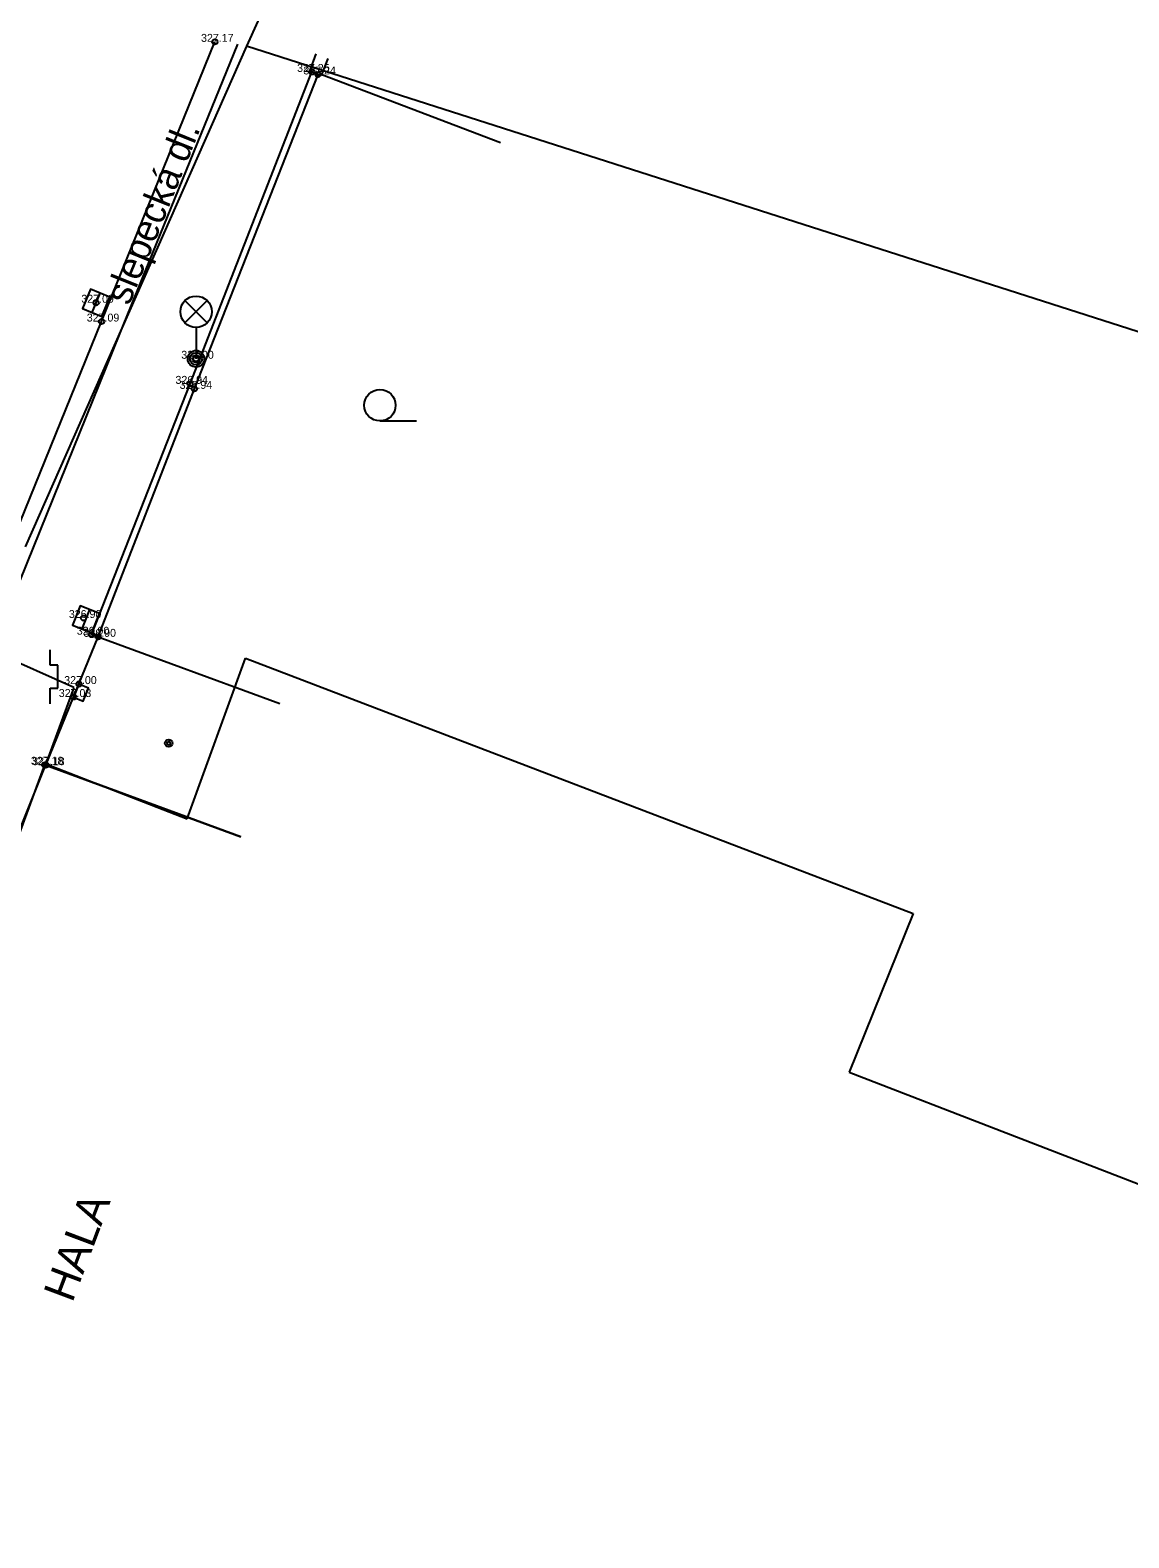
# Model space of a CAD drawing. Extents: x -643859 to -643594, y -1190913 to -1190609.
# Drawn here: x -643684.48 to -643658.2, y -1190805.4 to -1190769.34 of the extents above; entities that cross this region are included whole.
import ezdxf

# ---------------------------------------------------------------- set-up
doc = ezdxf.new("R2010")
doc.units = 0
for name, color, linetype in [('Bodové objekty elektro', 7, 'Continuous'), ('Bodové objekty kanalizace', 7, 'Continuous'), ('Bodové objekty katastrální', 7, 'Continuous'), ('Bodové objekty polohopis', 7, 'Continuous'), ('Bodové objekty značky budov', 7, 'Continuous'), ('Bodové objekty značky předmětů', 7, 'Continuous'), ('Budovy', 7, 'Continuous'), ('Default', 7, 'Continuous'), ('Hranice parcel', 7, 'Continuous'), ('Osa kolejí', 7, 'Continuous'), ('Ploty_podezdívky', 7, 'Continuous'), ('Popis povrchů', 7, 'Continuous'), ('Rozhraní', 7, 'Continuous'), ('Rozhraní_ schody_ zdi', 7, 'Continuous'), ('Svodidla_zábradlí', 7, 'Continuous')]:
    doc.layers.add(name, color=color, linetype=linetype)

msp = doc.modelspace()

# ---------------------------------------------------------------- linework, layer by layer
at = {"layer": 'Bodové objekty elektro'}
for p, q in [((-643683.999, -1190784.529), (-643684, -1190784.161)), ((-643683.816, -1190784.53), (-643683.999, -1190784.529)), ((-643683.816, -1190785.082), (-643683.816, -1190784.53)), ((-643684, -1190785.45), (-643683.999, -1190785.082)), ((-643683.999, -1190785.082), (-643683.816, -1190785.082))]:
    msp.add_line(p, q, dxfattribs=at)
at = {"layer": 'Bodové objekty kanalizace'}
for p, q in [((-643682.995, -1190776.091), (-643682.805, -1190775.629)), ((-643683.232, -1190783.662), (-643683.048, -1190783.198))]:
    msp.add_line(p, q, dxfattribs=at)
for points in [[(-643682.764, -1190776.186), (-643682.574, -1190775.724), (-643683.036, -1190775.534), (-643683.226, -1190775.996)], [(-643683, -1190783.754), (-643682.816, -1190783.29), (-643683.28, -1190783.106), (-643683.464, -1190783.57)]]:
    msp.add_lwpolyline(points, close=True, dxfattribs=at)
at = {"layer": 'Bodové objekty katastrální'}
msp.add_line((-643676.112, -1190778.688), (-643675.237, -1190778.688), dxfattribs=at)
msp.add_circle((-643676.112, -1190778.313), 0.375, dxfattribs=at)
at = {"layer": 'Bodové objekty polohopis'}
for p, q in [((-643680.775, -1190776.34), (-643680.245, -1190775.81)), ((-643680.775, -1190775.81), (-643680.245, -1190776.34)), ((-643680.51, -1190776.45), (-643680.51, -1190777.2))]:
    msp.add_line(p, q, dxfattribs=at)
for centre, radius in [((-643680.51, -1190776.075), 0.375), ((-643680.51, -1190777.2), 0.2), ((-643680.51, -1190777.2), 0.145), ((-643680.51, -1190777.2), 0.0876)]:
    msp.add_circle(centre, radius, dxfattribs=at)
at = {"layer": 'Bodové objekty značky budov'}
for radius in [0.09, 0.0398]:
    msp.add_circle((-643681.164, -1190786.394), radius, dxfattribs=at)
at = {"layer": 'Budovy'}
for points in [[(-643679.438, -1190788.637), (-643684.1, -1190786.92), (-643683.44, -1190785.29), (-643683.31, -1190784.98), (-643682.85, -1190783.85), (-643678.506, -1190785.449)], [(-643690.75, -1190804.15), (-643686.4, -1190792.73), (-643686.288, -1190792.773), (-643684.13, -1190786.91), (-643684.1, -1190786.92), (-643679.438, -1190788.637)]]:
    msp.add_lwpolyline(points, dxfattribs=at)
at = {"layer": 'Default'}
for centre in [(-643680.06, -1190769.62), (-643677.74, -1190770.34), (-643677.59, -1190770.4), (-643682.9, -1190775.86), (-643682.77, -1190776.31), (-643680.51, -1190777.2), (-643680.65, -1190777.8), (-643680.55, -1190777.92), (-643683.2, -1190783.4), (-643683.01, -1190783.8), (-643682.85, -1190783.85), (-643683.31, -1190784.98), (-643683.44, -1190785.29), (-643684.13, -1190786.91), (-643684.1, -1190786.92)]:
    msp.add_circle(centre, 0.0625, dxfattribs=at)
at = {"layer": 'Hranice parcel'}
for p, q in [((-643670.8, -1190750.82), (-643679.3, -1190769.72)), ((-643679.3, -1190769.72), (-643684.6, -1190781.7)), ((-643642.46, -1190781.53), (-643679.3, -1190769.72)), ((-643683.43, -1190785.06), (-643685.69, -1190784.06)), ((-643680.72, -1190788.2), (-643679.33, -1190784.36)), ((-643679.33, -1190784.36), (-643663.36, -1190790.47)), ((-643683.43, -1190785.06), (-643684.1, -1190786.89)), ((-643684.1, -1190786.89), (-643693.65, -1190810.62)), ((-643684.1, -1190786.89), (-643680.72, -1190788.2)), ((-643663.36, -1190790.47), (-643664.89, -1190794.26)), ((-643664.89, -1190794.26), (-643632.83, -1190806.65))]:
    msp.add_line(p, q, dxfattribs=at)
at = {"layer": 'Osa kolejí'}
msp.add_lwpolyline([(-643683.31, -1190784.98), (-643683.44, -1190785.29), (-643683.209, -1190785.387), (-643683.079, -1190785.077), (-643683.31, -1190784.98)], dxfattribs=at)
at = {"layer": 'Ploty_podezdívky'}
msp.add_line((-643677.511, -1190770.429), (-643677.354, -1190770.015), dxfattribs=at)
for points in [[(-643677.511, -1190770.429), (-643677.59, -1190770.4), (-643677.74, -1190770.34), (-643677.79, -1190770.32), (-643677.634, -1190769.91)], [(-643682.85, -1190783.85), (-643680.55, -1190777.92), (-643677.59, -1190770.4)], [(-643677.5, -1190770.4), (-643673.226, -1190772.031)]]:
    msp.add_lwpolyline(points, dxfattribs=at)
at = {"layer": 'Rozhraní'}
msp.add_lwpolyline([(-643693.72, -1190803.31), (-643690.856, -1190796.218), (-643685.61, -1190783.24), (-643685.45, -1190783.28), (-643685.1, -1190782.42), (-643685.22, -1190782.33), (-643682.77, -1190776.31), (-643680.06, -1190769.62)], dxfattribs=at)
at = {"layer": 'Rozhraní_ schody_ zdi'}
msp.add_line((-643680.65, -1190777.8), (-643677.74, -1190770.34), dxfattribs=at)
for points in [[(-643693.205, -1190803.493), (-643691.553, -1190799.413), (-643682.333, -1190776.603), (-643679.509, -1190769.675)], [(-643682.85, -1190783.85), (-643683.01, -1190783.8), (-643680.65, -1190777.8)]]:
    msp.add_lwpolyline(points, dxfattribs=at)

# ---------------------------------------------------------------- texts
at = {"layer": 'Bodové objekty značky předmětů'}
msp.add_text('HALA', height=0.75, rotation=69.3748, dxfattribs=at).set_placement((-643683.471, -1190799.796))
at = {"layer": 'Popis povrchů'}
msp.add_text('slepecká dl.', height=0.64999, rotation=68.0617, dxfattribs=at).set_placement((-643682.111, -1190775.947))
at = {"layer": 'Svodidla_zábradlí'}
for s, p in [('327.17', (-643680.39, -1190769.62)), ('327.25', (-643678.093, -1190770.34)), ('327.24', (-643677.943, -1190770.4)), ('327.09', (-643683.253, -1190775.86)), ('327.09', (-643683.123, -1190776.31)), ('327.00', (-643680.863, -1190777.2)), ('326.94', (-643681.002, -1190777.8)), ('326.94', (-643680.902, -1190777.92)), ('326.90', (-643683.552, -1190783.4)), ('326.90', (-643683.362, -1190783.8)), ('326.90', (-643683.202, -1190783.85)), ('327.00', (-643683.663, -1190784.98)), ('327.03', (-643683.793, -1190785.29)), ('327.18', (-643684.46, -1190786.91)), ('327.18', (-643684.43, -1190786.92))]:
    msp.add_text(s, height=0.19, dxfattribs=at).set_placement(p)

doc.saveas('drawing.dxf')
